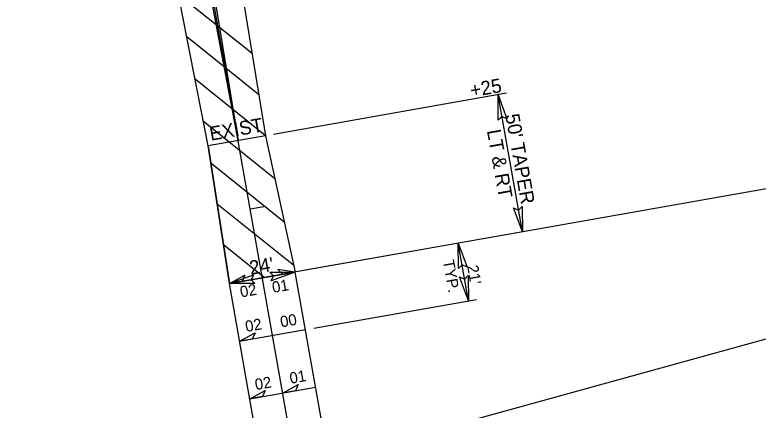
# Model space of a CAD drawing. Extents: x 1762196 to 1766326, y 709922 to 713142.
# Drawn here: x 1763863.7 to 1764130.5, y 711859.4 to 712001.2 of the extents above; entities that cross this region are included whole.
import ezdxf

# ---------------------------------------------------------------- set-up
doc = ezdxf.new("R2010")
doc.units = 0
for name, color, linetype in [('Old_Level_40', 7, 'Continuous'), ('Prop Dimension', 7, 'Continuous'), ('Prop EOT', 7, 'Continuous'), ('Prop Horizontal Alignment', 7, 'Continuous'), ('Prop Horizontal Alignment Station Label', 7, 'Continuous'), ('Prop Horizontal Alignment Tick Small', 7, 'Continuous'), ('Prop Lane Lines', 7, 'Continuous'), ('Prop Superelevation  Arrow CELL', 7, 'Continuous'), ('Prop Superelevation Label', 7, 'Continuous'), ('Prop Terminator CELL', 7, 'Continuous')]:
    doc.layers.add(name, color=color, linetype=linetype)

msp = doc.modelspace()

# ---------------------------------------------------------------- linework, layer by layer
at = {"layer": 'Old_Level_40'}
for p, q in [((1763943.94, 712017.75), (1763953.64, 711957.83)), ((1763922.76, 712008.38), (1763948.84, 711987.5)), ((1763933.12, 711954.2), (1763922.95, 712006.03)), ((1763925.42, 711993.44), (1763951.22, 711972.78)), ((1763928.4, 711978.24), (1763953.6, 711958.06)), ((1763931.38, 711963.05), (1763957, 711942.53)), ((1763953.64, 711957.83), (1763964.38, 711908.95)), ((1763940.75, 711904.78), (1763933.12, 711954.2)), ((1763934.06, 711948.09), (1763960.42, 711926.98)), ((1763936.32, 711933.47), (1763963.83, 711911.44)), ((1763938.57, 711918.85), (1763953.37, 711907.01)), ((1763964.38, 711908.95), (1763940.75, 711904.78))]:
    msp.add_line(p, q, dxfattribs=at)
at = {"layer": 'Prop Dimension'}
for p, q in [((1764040.16, 711973.12), (1763956.56, 711958.35)), ((1764045.9, 711923.36), (1764037.2, 711972.6)), ((1764048.86, 711923.88), (1763967.33, 711909.48)), ((1763964.38, 711908.95), (1763940.75, 711904.78))]:
    msp.add_line(p, q, dxfattribs=at)
at = {"layer": 'Prop EOT'}
for p, q in [((1763953.64, 711957.83), (1763933.12, 711954.2)), ((1763953.64, 711957.83), (1763964.38, 711908.95)), ((1763933.12, 711954.2), (1763940.75, 711904.78)), ((1763978.74, 711827.69), (1763964.38, 711908.95)), ((1763955.68, 711820.27), (1763940.75, 711904.78))]:
    msp.add_line(p, q, dxfattribs=at)
at = {"layer": 'Prop Horizontal Alignment'}
msp.add_line((1763966.92, 711825.6), (1763863.71, 712409.75), dxfattribs=at)
at = {"layer": 'Prop Horizontal Alignment Station Label'}
for p, q in [((1764261.77, 711961.49), (1763953.16, 711906.98)), ((1763964.65, 711838.46), (1764174.02, 711896.16))]:
    msp.add_line(p, q, dxfattribs=at)
at = {"layer": 'Prop Horizontal Alignment Tick Small'}
msp.add_line((1763953.14, 711932.35), (1763948.21, 711931.48), dxfattribs=at)
at = {"layer": 'Prop Lane Lines'}
for p, q in [((1763943.86, 711956.1), (1763902.01, 712177.19)), ((1763907.42, 712178.15), (1763943.86, 711956.1))]:
    msp.add_line(p, q, dxfattribs=at)
at = {"layer": 'Prop Superelevation  Arrow CELL'}
for points in [[(1763940.75, 711904.78), (1763946.31, 711907.79), (1763945.3, 711905.58)], [(1763964.38, 711908.95), (1763958.12, 711909.88), (1763959.83, 711908.15)], [(1763944.4, 711884.1), (1763949.96, 711887.11), (1763948.95, 711884.9)], [(1763959.87, 711865.51), (1763965.43, 711868.52), (1763964.43, 711866.31)], [(1763948.05, 711863.42), (1763953.61, 711866.43), (1763952.61, 711864.22)]]:
    msp.add_lwpolyline(points, close=True, dxfattribs=at)
at = {"layer": 'Prop Superelevation Label'}
for p, q in [((1764026.52, 711898.61), (1764022.87, 711919.29)), ((1763940.75, 711904.78), (1763964.38, 711908.95)), ((1763970.99, 711888.8), (1764029.47, 711899.13)), ((1763944.4, 711884.1), (1763968.03, 711888.27)), ((1763948.05, 711863.42), (1763971.69, 711867.59))]:
    msp.add_line(p, q, dxfattribs=at)
at = {"layer": 'Prop Terminator CELL'}
for points in [[(1764037.24, 711963.46), (1764037.2, 711972.6), (1764040.35, 711963.96), (1764038.58, 711964.82)], [(1764045.86, 711932.49), (1764045.9, 711923.36), (1764042.75, 711931.99), (1764044.53, 711931.14)], [(1764022.91, 711910.16), (1764022.87, 711919.29), (1764026.02, 711910.65), (1764024.24, 711911.51)], [(1763949.88, 711904.82), (1763940.75, 711904.78), (1763949.38, 711907.93), (1763948.53, 711906.15)], [(1763955.25, 711908.91), (1763964.38, 711908.95), (1763955.75, 711905.8), (1763956.6, 711907.58)], [(1764026.48, 711907.74), (1764026.52, 711898.61), (1764023.37, 711907.24), (1764025.15, 711906.39)]]:
    msp.add_lwpolyline(points, close=True, dxfattribs=at)

# ---------------------------------------------------------------- texts
at = {"layer": 'Prop Dimension'}
for s, rotation, p in [('+25', 10.0204, (1764027.6, 711971.62)), ('EXIST', 10.0204, (1763934.04, 711956.05)), ("50' TAPER", 280.0204, (1764039.77, 711965.31)), ('LT & RT', 280.0204, (1764033.15, 711959.7)), ("24'", 10.0204, (1763948.38, 711907.92))]:
    msp.add_text(s, height=5, rotation=rotation, dxfattribs=at).set_placement(p)
at = {"layer": 'Prop Superelevation Label'}
for s, rotation, p in [('TYP.', 280.0204, (1764017.35, 711912.98)), ("21'", 280.0204, (1764026.04, 711911.1)), ('02', 10.0204, (1763944.91, 711899.79)), ('01', 10.0204, (1763956.41, 711901.42)), ('00', 10.0204, (1763959.33, 711889.04)), ('02', 10.0204, (1763946.78, 711887.39)), ('01', 10.0204, (1763962.69, 711868.8)), ('02', 10.0204, (1763950.24, 711866.54))]:
    msp.add_text(s, height=4, rotation=rotation, dxfattribs=at).set_placement(p)

doc.saveas('drawing.dxf')
